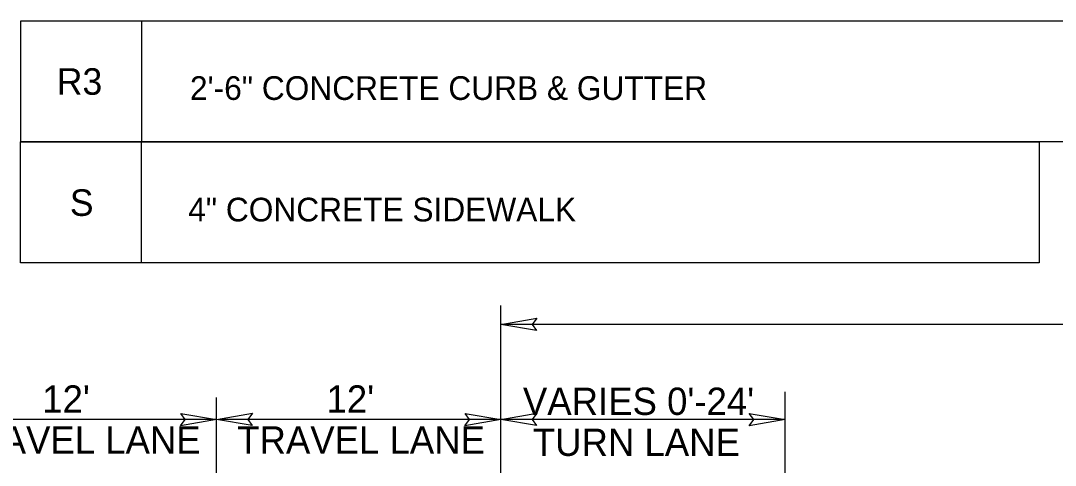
# Model space of a CAD drawing. Extents: x 2176024 to 2177225, y 75947 to 76635.
# Drawn here: x 2176725.57 to 2176769.25, y 76566.01 to 76584.79 of the extents above; entities that cross this region are included whole.
import ezdxf

# ---------------------------------------------------------------- set-up
doc = ezdxf.new("R2010")
doc.units = 0
for name, color, linetype in [('Prop Dimension', 7, 'Continuous'), ('Prop Pavement Schedule Description CELL', 7, 'Continuous'), ('Typical Terminator CELL', 7, 'Continuous'), ('Typical Text General CELL', 7, 'Continuous')]:
    doc.layers.add(name, color=color, linetype=linetype)

msp = doc.modelspace()

# ---------------------------------------------------------------- linework, layer by layer
at = {"layer": 'Prop Dimension'}
for p, q in [((2176745.841, 76561.7), (2176745.841, 76572.767)), ((2176805.841, 76571.958), (2176745.841, 76571.958)), ((2176733.841, 76555.644), (2176733.841, 76568.874)), ((2176757.841, 76553.567), (2176757.841, 76569.109)), ((2176733.841, 76567.947), (2176721.947, 76567.947)), ((2176745.841, 76567.947), (2176733.947, 76567.947)), ((2176757.841, 76567.947), (2176745.841, 76567.947))]:
    msp.add_line(p, q, dxfattribs=at)
at = {"layer": 'Prop Pavement Schedule Description CELL'}
for points in [[(2176730.689, 76579.671), (2176725.575, 76579.671), (2176725.575, 76584.785), (2176794.118, 76584.785), (2176794.118, 76579.671), (2176730.689, 76579.671), (2176730.689, 76584.785)], [(2176730.68, 76574.562), (2176725.566, 76574.562), (2176725.566, 76579.677), (2176768.564, 76579.677), (2176768.564, 76574.562), (2176730.68, 76574.562), (2176730.68, 76579.677)]]:
    msp.add_lwpolyline(points, dxfattribs=at)
at = {"layer": 'Typical Terminator CELL'}
for points in [[(2176747.35, 76571.698), (2176745.841, 76571.958), (2176747.359, 76572.226), (2176747.166, 76571.958)], [(2176732.331, 76568.207), (2176733.841, 76567.947), (2176732.323, 76567.678), (2176732.516, 76567.947)], [(2176735.35, 76567.687), (2176733.841, 76567.947), (2176735.359, 76568.215), (2176735.166, 76567.947)], [(2176744.331, 76568.207), (2176745.841, 76567.947), (2176744.323, 76567.678), (2176744.516, 76567.947)], [(2176747.35, 76567.687), (2176745.841, 76567.947), (2176747.359, 76568.215), (2176747.166, 76567.947)], [(2176756.331, 76568.207), (2176757.841, 76567.947), (2176756.323, 76567.678), (2176756.516, 76567.947)]]:
    msp.add_lwpolyline(points, close=True, dxfattribs=at)

# ---------------------------------------------------------------- texts
at = {"layer": 'Prop Pavement Schedule Description CELL'}
for s, height, p in [('R3', 1.12, (2176727.101, 76581.658)), ('2\'-6" CONCRETE CURB & GUTTER', 1, (2176732.719, 76581.44)), ('S', 1.12, (2176727.65, 76576.544)), ('4" CONCRETE SIDEWALK', 1, (2176732.645, 76576.31))]:
    msp.add_text(s, height=height, dxfattribs=at).set_placement(p)
at = {"layer": 'Typical Text General CELL'}
for s, height, p in [("12' ", 1.1533, (2176726.485, 76568.235)), ("12' ", 1.1533, (2176738.485, 76568.235)), ("VARIES 0'-24'", 1.15334, (2176746.775, 76568.139)), ('TRAVEL LANE', 1.15334, (2176722.715, 76566.505)), ('TRAVEL LANE', 1.15334, (2176734.715, 76566.505)), (' TURN LANE', 1.1533, (2176746.766, 76566.409))]:
    msp.add_text(s, height=height, dxfattribs=at).set_placement(p)

doc.saveas('drawing.dxf')
